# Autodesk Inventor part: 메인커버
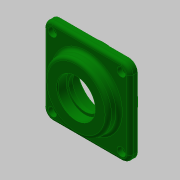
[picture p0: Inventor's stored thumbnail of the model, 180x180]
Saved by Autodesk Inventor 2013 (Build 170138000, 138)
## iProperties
Created: 2018-09
Part Number: 메인커버
Material: 일반
Document SubType Name: Modeling
Designer: mduedu
Density: 1 g/cm^3
Author: mduedu
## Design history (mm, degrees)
sketch "스케치1"
  geometry: L1 (-40, -40)-(40, -40); L2 (40, -40)-(40, 40); L3 (40, 40)-(-40, 40); L4 (-40, 40)-(-40, -40); L5 (-40, -40)-(40, 40); L6 (40, -40)-(-40, 40); 1 further point
  constraints: 12 end point, 2 midpoint, 2 parallel, 1 horizontal, 1 perpendicular
  dimensions: "d0" = 80 distance of L3.end L2.end; "d1" = 80 distance of L2.end L1.end
extrude "돌출1" new body sketch "스케치1" distance "d2" = 7; taper "d3" = 0 deg
sketch "스케치2"
  geometry: C1 r 30 at (0, 0); 1 further point
  constraints: 1 centre point, 1 coincident
  dimensions: "d4" = 60 diameter of C1
extrude "돌출2" join sketch "스케치2" distance "d5" = 10; taper "d6" = 0 deg
sketch "스케치3"
  geometry: C1 r 32.5 at (0, 0); 1 further point
  constraints: 1 centre point, 1 coincident
  dimensions: "d7" = 65 diameter of C1
extrude "돌출3" join sketch "스케치3" distance "d8" = 9; taper "d9" = 0 deg
sketch "스케치4"
  geometry: L1 (-32.5, -9)-(32.5, -9) reference; L2 (30, 17)-(-30, 17) reference; L3 (0, 17)-(0, -9); L4 (0, -9)-(23.5, -9); L5 (23.5, -9)-(23.5, 5); L6 (23.5, 5)-(0, 5); L7 (0, 5)-(0, -9); L8 (0, 5)-(15, 5); L9 (15, 5)-(15, 8.7); L10 (15, 8.7)-(0, 8.7); L11 (0, 8.7)-(0, 5); L12 (0, 8.7)-(17.5, 8.7); L13 (17.5, 8.7)-(17.5, 17); L14 (17.5, 17)-(0, 17); L15 (0, 17)-(0, 8.7); 1 further point
  constraints: 26 end point, 6 parallel, 3 horizontal, 3 perpendicular, 2 midpoint, 1 point on line
  dimensions: "d10" = 14 distance of L4.end L5.end; "d12" = 8.3 distance of L12.end L13.end; "d13" = 35 diameter of L13 L3; "d14" = 30 diameter of L9 L3; "d15" = 47 diameter of L5 L3
revolve "회전1" sketch "스케치4" stored, may be unused: angle "d16" = 90 deg
fillet "모깎기1" dims "d17" = 8
fillet "모깎기2" dims "d18" = 3
fillet "모깎기3" dims "d19" = 3
chamfer "모따기1" distance "d20" = 0.8; stored, may be unused: second distance "d21" = 2, angle "d22" = 30 deg
chamfer "모따기2" distance "d23" = 1; stored, may be unused: second distance "d24" = 2, angle "d25" = 30 deg
fillet "모깎기4" dims "d26" = 0.3
sketch "스케치5"
  geometry: A1 r 8 centre (-32, 32) between (-32, 40) and (-40, 32) reference; A2 r 8 centre (-32, -32) between (-40, -32) and (-32, -40) reference; A3 r 8 centre (32, -32) between (32, -40) and (40, -32) reference; A4 r 8 centre (32, 32) between (40, 32) and (32, 40) reference; 5 further points
  constraints: 4 coincident
hole "구멍1" sketch "스케치5" at (-32, 32), (32, 32), (32, -32), (-32, -32) diameter "d27" = 4.5; stored, may be unused: countersink angle "d31" = 90 deg, drill point angle "d33" = 118 deg; dims "d28" = 6, "d29" = 8, "d30" = 4.4, "d32" = 8
node "솔리드1"
